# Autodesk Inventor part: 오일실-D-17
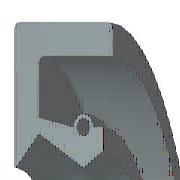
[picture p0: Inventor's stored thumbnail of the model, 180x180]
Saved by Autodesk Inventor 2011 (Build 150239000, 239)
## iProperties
IsCustomPart: 0
Company: 한국ATC센터
Created: 2014-12
Part Number: 오일실-D-17
Material: 고무
Description: 오일-실
Document SubType Name: Modeling
Standard: KS B 2804
Designer: KYOUNG IL JANG
Standards Organization: KS
Language: ko-KR
Size Designation: D - 17 30 8
Categories: <MemberInstance><Categories><Category DisplayName="샤프트 부품" InternalName="7f7aeb1f-a693-4053-b835-cee3144e0d98" Mnemonic="SHFT"><Category DisplayName="실링" Intern
Density: 0.93 g/cm^3
Mass: 2.05797 g
Surface Area: 29.3036 cm^2
Volume: 2.21288 cm^3
Author: KYOUNG IL JANG
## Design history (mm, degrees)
revolve "본체" stored, may be unused: angle "d17" = 90 deg
revolve "스프링1" stored, may be unused: angle "d18" = 90 deg
body "Solid1"
sketch "스케치1"
  geometry: L1 (0, 15)-(8, 15); L2 (8, 13.25)-(1.75, 13.25); L3 (1.75, 10.25)-(4.9, 8.5); L4 (4.9, 8.5)-(0, 8.5); L5 (0, 0)-(9.586, 0) reference; L6 (4.9, 8.5)-(6.3, 9.375); L7 (0, 18)-(0, -3) reference; L8 (-1.941, 0)-(11.507, 0) reference; L9 (4.2, 10.6)-(1.75, 11.21); L10 (1.75, 11.21)-(1.75, 13.25); L11 (0, 15)-(0, 8.588); L12 (4.9, 8.5)-(0, 8.5); L13 (1.75, 10.25)-(0.152, 8.528); L14 (8, 15)-(8, 13.25); L15 (5.6, 10.6)-(6.3, 10.6); L16 (6.3, 10.6)-(6.3, 9.375); C1 r 0.455 at (4.9, 10.6); A1 r 0.7 centre (4.9, 10.6) between (5.6, 10.6) and (4.2, 10.6); A2 r 0.088 centre (0.088, 8.588) between (0, 8.588) and (0.152, 8.528); 1 further point
  constraints: 28 end point, 5 horizontal alignment, 5 point on line, 4 point on circle, 4 vertical alignment, 3 centre point, 3 tangent, 2 collinear, 2 horizontal, 2 perpendicular, 1 coincident, 1 parallel
  dimensions: "d0" = 30 diameter of L1 L5 (= SD2); "d1" = 1.75 distance of L1.end L2.start (= SD); "d2" = 0.91 diameter of C1 (= SPDI); "d3" = 1.4 diameter of A1 (= SPDA); "d4" = 17 diameter of L3.end L5 (= NND); "d5" = 20.5 diameter of L3.start L5 (= TKDM); "d7" = 22.42 diameter of L9.end L5 (= TKDM + 0.24 x SWDT); "d8" = 1.75 distance between parallel lines of L11 L10 (= SD); "d9" = 4.9 distance from line of L11 C1.centre (= SPDST); "d10" = 21.2 diameter of C1.centre L5 (= HLDM); "d11" = 0.0875 radius of A2 (= 0.25 x LAB); "d12" = 6.3 distance between parallel lines of L11 L16 (= SDI); "d13" = 18.75 diameter of L6.end L5 (= ABDM); "d14" = 8 distance from line of L11 L1.end (= SWDT)
fillet "모깎기1" dims "d6" = 0.3 (= RR)
other parameters: "SD2" = 30 [user parameter; used in 1 equation term], "SWDT" = 8 [user parameter; used in 2 equation terms], "RR" = 0.3 [user parameter; used in 1 equation term], "SD" = 1.75 [user parameter; used in 2 equation terms], "NND" = 17 [user parameter; used in 1 equation term], "SPDA" = 1.4 [user parameter; used in 1 equation term], "SPDI" = 0.91 [user parameter; used in 1 equation term], "TKDM" = 20.5 [user parameter; used in 2 equation terms], "HLDM" = 21.2 [user parameter; used in 1 equation term], "ABDM" = 18.75 [user parameter; used in 1 equation term], "SDI" = 6.3 [user parameter; used in 1 equation term], "SPDST" = 4.9 [user parameter; used in 1 equation term], "LAB" = 0.35 [user parameter; used in 1 equation term], "d15" = 0, "d16" = 0, "d19" = 0
